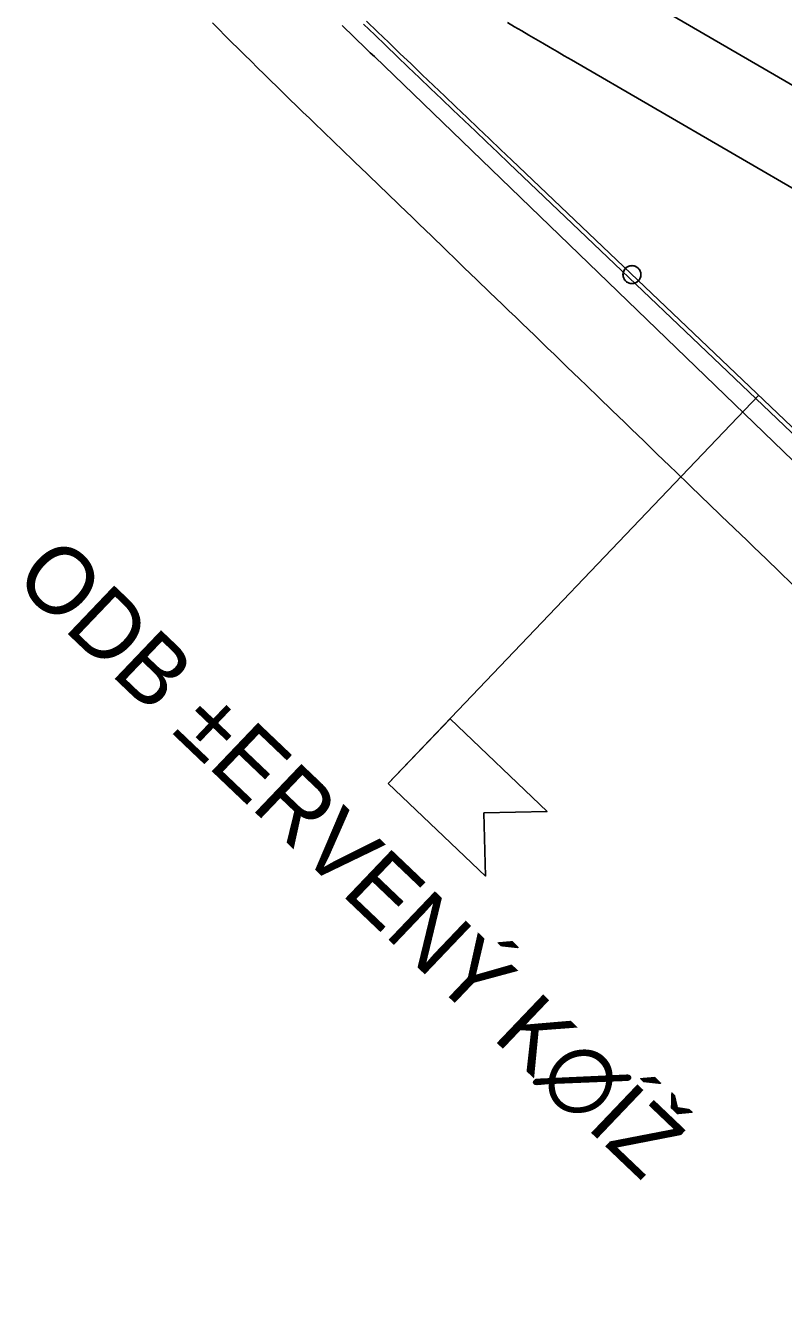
# Model space of a CAD drawing. Extents: x -670810 to -649614, y -1131928 to -1115069.
# Drawn here: x -668416 to -667569, y -1124610 to -1123186 of the extents above; entities that cross this region are included whole.
import ezdxf

# ---------------------------------------------------------------- set-up
doc = ezdxf.new("R2010")
doc.units = 0
for name, color, linetype in [('519 Var SK-4 Praporky stanic', 7, 'Continuous'), ('hranice_VRT_ZUR_Vysocina', 7, 'Continuous'), ('Situace - Osa koleje 2D', 7, 'Continuous'), ('Staničení - hlavní staničení + kolečka 1k', 7, 'Continuous')]:
    doc.layers.add(name, color=color, linetype=linetype)

# ---------------------------------------------------------------- blocks, each defined once
blk = doc.blocks.new('Sit10Kruh_106')
at = {"layer": 'Staničení - hlavní staničení + kolečka 1k'}
blk.add_lwpolyline([(10, 0), (10, 0.6), (9.9, 1.3), (9.8, 1.9), (9.7, 2.5), (9.5, 3.1), (9.3, 3.7), (9, 4.3), (8.8, 4.8), (8.4, 5.4), (8.1, 5.9), (7.7, 6.4), (7.3, 6.8), (6.8, 7.3), (6.4, 7.7), (5.9, 8.1), (5.4, 8.4), (4.8, 8.8), (4.3, 9), (3.7, 9.3), (3.1, 9.5), (2.5, 9.7), (1.9, 9.8), (1.3, 9.9), (0.6, 10), (0, 10), (-0.6, 10), (-1.3, 9.9), (-1.9, 9.8), (-2.5, 9.7), (-3.1, 9.5), (-3.7, 9.3), (-4.3, 9), (-4.8, 8.8), (-5.4, 8.4), (-5.9, 8.1), (-6.4, 7.7), (-6.8, 7.3), (-7.3, 6.8), (-7.7, 6.4), (-8.1, 5.9), (-8.4, 5.4), (-8.8, 4.8), (-9, 4.3), (-9.3, 3.7), (-9.5, 3.1), (-9.7, 2.5), (-9.8, 1.9), (-9.9, 1.3), (-10, 0.6), (-10, 0), (-10, -0.6), (-9.9, -1.3), (-9.8, -1.9), (-9.7, -2.5), (-9.5, -3.1), (-9.3, -3.7), (-9, -4.3), (-8.8, -4.8), (-8.4, -5.4), (-8.1, -5.9), (-7.7, -6.4), (-7.3, -6.8), (-6.8, -7.3), (-6.4, -7.7), (-5.9, -8.1), (-5.4, -8.4), (-4.8, -8.8), (-4.3, -9), (-3.7, -9.3), (-3.1, -9.5), (-2.5, -9.7), (-1.9, -9.8), (-1.3, -9.9), (-0.6, -10), (0, -10), (0.6, -10), (1.3, -9.9), (1.9, -9.8), (2.5, -9.7), (3.1, -9.5), (3.7, -9.3), (4.3, -9), (4.8, -8.8), (5.4, -8.4), (5.9, -8.1), (6.4, -7.7), (6.8, -7.3), (7.3, -6.8), (7.7, -6.4), (8.1, -5.9), (8.4, -5.4), (8.8, -4.8), (9, -4.3), (9.3, -3.7), (9.5, -3.1), (9.7, -2.5), (9.8, -1.9), (9.9, -1.3)], close=True, dxfattribs=at)
blk.add_circle((0, 0), 10, dxfattribs=at)

msp = doc.modelspace()

# ---------------------------------------------------------------- linework, layer by layer
at = {"layer": '519 Var SK-4 Praporky stanic'}
msp.add_line((-667596.8, -1123599.7), (-668010.7, -1124033.8), dxfattribs=at)
msp.add_lwpolyline([(-668010.7, -1124033.8), (-667902.2, -1124137.3), (-667903.9, -1124066.6), (-667833.2, -1124064.9), (-667941.7, -1123961.4)], close=True, dxfattribs=at)
at = {"layer": 'hranice_VRT_ZUR_Vysocina'}
for points in [[(-667764.4, -1123133), (-666960.3, -1123600.4)], [(-668207.3, -1123183.1), (-668200.1, -1123190.3), (-668193, -1123197.5), (-668185.8, -1123204.6), (-668178.6, -1123211.8), (-668171.4, -1123219), (-668164.1, -1123226.1), (-668156.9, -1123233.3), (-668149.6, -1123240.4), (-668142.4, -1123247.5), (-668135.1, -1123254.6), (-668132, -1123257.7), (-668127.8, -1123261.7), (-668120.6, -1123268.7), (-668113.3, -1123275.8), (-668106.1, -1123282.8), (-668098.9, -1123289.7), (-668095.8, -1123292.7), (-668091.7, -1123296.7), (-668084.5, -1123303.6), (-668070.1, -1123317.5), (-668062.9, -1123324.5), (-668048.5, -1123338.4), (-668034.1, -1123352.3), (-668019.7, -1123366.2), (-668012.5, -1123373.1), (-667998.2, -1123387), (-667983.8, -1123400.9), (-667976.6, -1123407.8), (-667962.2, -1123421.7), (-667947.8, -1123435.6), (-667933.4, -1123449.5), (-667926.2, -1123456.5), (-667911.8, -1123470.4), (-667897.5, -1123484.2), (-667883.1, -1123498.1), (-667875.9, -1123505.1), (-667868.7, -1123512), (-667861.5, -1123519), (-667847.1, -1123532.9), (-667839.9, -1123539.8), (-667832.7, -1123546.8), (-667825.5, -1123553.7), (-667818.3, -1123560.7), (-667811.1, -1123567.6), (-667796.8, -1123581.5), (-667789.6, -1123588.4), (-667775.2, -1123602.3), (-667760.8, -1123616.2), (-667746.4, -1123630.1), (-667739.2, -1123637.1), (-667724.8, -1123651), (-667710.4, -1123664.9), (-667696, -1123678.8), (-667688.9, -1123685.7), (-667674.5, -1123699.6), (-667660.1, -1123713.5), (-667652.9, -1123720.4), (-667638.5, -1123734.3), (-667624.1, -1123748.2), (-667609.7, -1123762.1), (-667602.5, -1123769.1), (-667588.1, -1123783), (-667573.8, -1123796.8), (-667559.4, -1123810.7)]]:
    msp.add_lwpolyline(points, dxfattribs=at)
at = {"layer": 'Situace - Osa koleje 2D'}
for p, q in [((-668026.3, -1123220.8), (-667266.8, -1123954.3)), ((-667806, -1123224.5), (-667012.6, -1123685.7)), ((-667875.9, -1123340), (-664682.6, -1126385.2)), ((-667872.7, -1123336.5), (-664677.5, -1126383.5))]:
    msp.add_line(p, q, dxfattribs=at)
for points in [[(-668062.2, -1123186), (-668057.7, -1123190.4), (-668053.3, -1123194.7), (-668048.8, -1123199.1), (-668044.3, -1123203.4), (-668039.8, -1123207.8), (-668035.3, -1123212.1), (-668030.8, -1123216.5), (-668026.3, -1123220.8)], [(-668038.3, -1123184.6), (-668025.8, -1123196.6), (-668013.4, -1123208.6), (-668000.9, -1123220.6), (-667988.4, -1123232.5), (-667975.9, -1123244.5), (-667963.5, -1123256.4), (-667951, -1123268.4), (-667938.5, -1123280.3), (-667926, -1123292.2), (-667913.4, -1123304.2), (-667900.9, -1123316.1), (-667888.4, -1123328), (-667875.9, -1123340)], [(-668035, -1123181.2), (-668022.6, -1123193.2), (-668010.1, -1123205.2), (-667997.7, -1123217.2), (-667985.2, -1123229.1), (-667972.7, -1123241.1), (-667960.2, -1123253), (-667947.7, -1123264.9), (-667935.2, -1123276.9), (-667922.7, -1123288.8), (-667910.2, -1123300.7), (-667897.7, -1123312.7), (-667885.2, -1123324.6), (-667872.7, -1123336.5)], [(-667877.5, -1123182.8), (-667869.6, -1123187.4), (-667861.6, -1123192.1), (-667853.7, -1123196.7), (-667845.8, -1123201.4), (-667837.8, -1123206), (-667829.9, -1123210.6), (-667821.9, -1123215.3), (-667814, -1123219.9), (-667806, -1123224.5)]]:
    msp.add_lwpolyline(points, dxfattribs=at)

# ---------------------------------------------------------------- block references
at = {"layer": 'Staničení - hlavní staničení + kolečka 1k', "rotation": -43.640410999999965}
msp.add_blockref('Sit10Kruh_106', (-667738.4, -1123464.6), dxfattribs=at)

# ---------------------------------------------------------------- texts
at = {"layer": '519 Var SK-4 Praporky stanic'}
msp.add_text('ODB ±ERVENÝ K∅ÍŽ', height=75, rotation=316.3596, dxfattribs=at).set_placement((-668431.3, -1123807.1))

doc.saveas('drawing.dxf')
